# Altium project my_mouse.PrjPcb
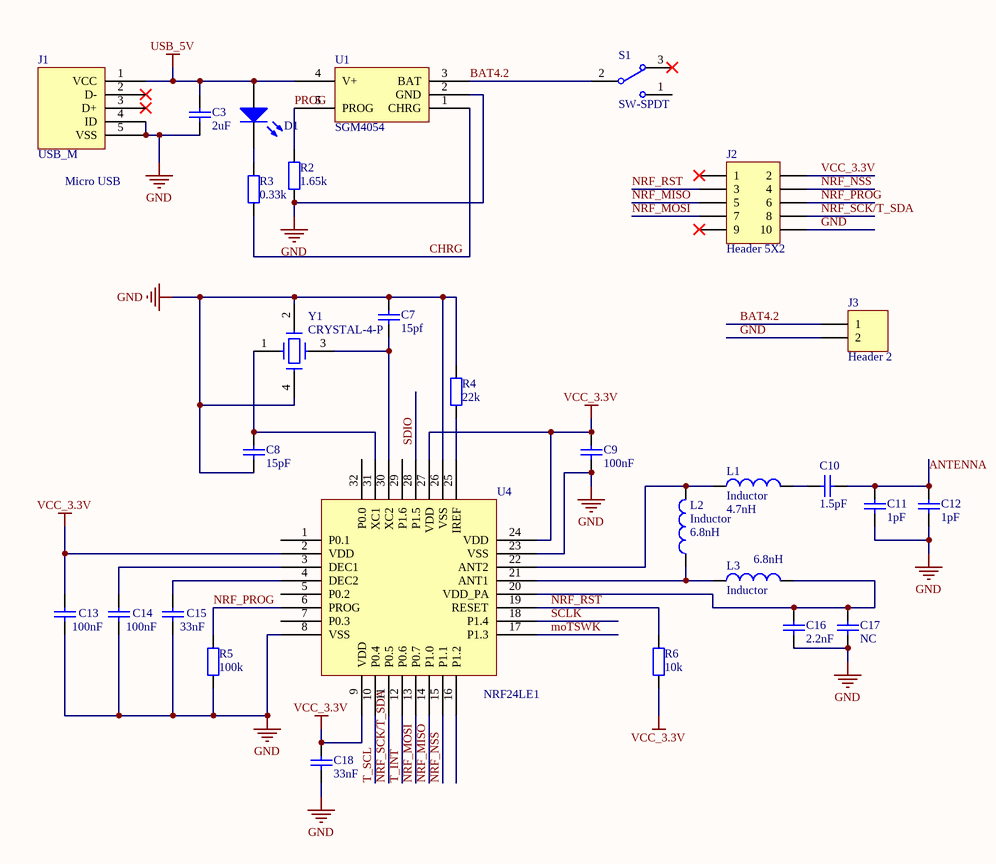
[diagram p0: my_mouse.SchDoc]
1 sheet, 29 parts. Net scope: global (net labels, ports and power ports of the same name join across sheets).
Board file: my_mouse.PcbDoc

## Sheet my_mouse.SchDoc
size A4

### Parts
C3  value 2uF  [C-0603]  (hidden comment: Cap-S)
C7  value 15pf  [0402s]  (hidden comment: Cap-S)
C8  value 15pF  [0402s]  (hidden comment: Cap-S)
C9  value 100nF  [0402s]  (hidden comment: Cap-S)
C10  value 1.5pF  [0402s]  (hidden comment: Cap-S)
C11  value 1pF  [0402s]  (hidden comment: Cap-S)
C12  value 1pF  [0402s]  (hidden comment: Cap-S)
C13  value 100nF  [0402s]  (hidden comment: X7R 16V)
C14  value 100nF  [0402s]  (hidden comment: X7R 16V)
C15  value 33nF  [0402s]  (hidden comment: X7R 16V)
C16  value 2.2nF  [0402s]  (hidden comment: Cap-S)
C17  value NC  [0402s]  (hidden comment: Cap-S)
C18  value 33nF  [0402s]  (hidden comment: Cap-S)
D1  LED0  [LED-0805]  (value not drawn)
J1  USB_M  [USB_MICRO]
J2  Header 5X2  [HEAD2X5_0.2]
J3  Header 2  [head2_2.0]
L1  Inductor  value 4.7nH  [0402s]
L2  Inductor  value 6.8nH  [0402s]
L3  Inductor  value 6.8nH  [0402s]
R2  value 1.65k  [0603-1]  (hidden comment: Res1)
R3  value 0.33k  [0603-1]  (hidden comment: Res1)
R4  value 22k  [0402s]  (hidden comment: Res1)
R5  value 100k  [0402s]  (hidden comment: Res1)
R6  value 10k  [0402s]  (hidden comment: Res1)
S1  SW-SPDT  [三脚拨动开关2]
U1  SGM4054  [SGM4054]
U4  NRF24LE1  [Nordic_QFN50P500X500X90-33N]
Y1  CRYSTAL-4-P  [OSC3225]

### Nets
GND: C3.1 C7.2 C8.1 C9.1 C11.2 C12.2 C13.1 C14.1 C15.1 C16.1 C17.1 C18.1 J1.4(ID) J1.5(VSS) J2.10 J3.2 R2.1 R4.2 R5.1 U1.2(GND) U4.8(VSS) U4.23(VSS) U4.26(VSS) Y1.2 Y1.4
USB_5V: C3.2 D1.1(A) J1.1(VCC) U1.4(V+)
VCC_3.3V: C9.2 C13.2 C18.2 J2.2 R6.1 U4.2(VDD) U4.9(VDD) U4.24(VDD) U4.27(VDD)
ANTENNA: C10.1 C11.1 C12.1
BAT4.2: J3.1 S1.2 U1.3(BAT)
CHRG: R3.1 U1.1(CHRG)
moTSWK: U4.17(P1.3)
NRF_MISO: J2.5 U4.14(P1.0)
NRF_MOSI: J2.7 U4.13(P0.7)
NRF_NSS: J2.4 U4.15(P1.1)
NRF_PROG: J2.6 R5.2 U4.6(PROG)
NRF_RST: J2.3 R6.2 U4.19(RESET)
NRF_SCK/T_SDA: J2.8 U4.11(P0.5)
PROG: R2.2 U1.5(PROG)
SCLK: U4.18(P1.4)
SDIO: U4.28(P1.5)
T_INT: U4.12(P0.6)
T_SCL: U4.10(P0.4)
NetC7_1: C7.1 U4.30(XC2) Y1.3
NetC8_2: C8.2 U4.31(XC1) Y1.1
NetC10_2: C10.2 L1.2
NetC14_2: C14.2 U4.3(DEC1)
NetC15_2: C15.2 U4.4(DEC2)
NetC16_2: C16.2 C17.2 L3.2 U4.20(VDD_PA)
NetD1_2: D1.2(K) R3.2
NetL1_1: L1.1 L2.2 U4.22(ANT2)
NetL2_1: L2.1 L3.1 U4.21(ANT1)
NetR4_1: R4.1 U4.25(IREF)

Not connected (* = marked no-connect by the designer): J1 2(D-)* 3(D+)*; J2 1* 9*; S1 1 3*; U4 1(P0.1) 5(P0.2) 7(P0.3) 16(P1.2) 29(P1.6) 32(P0.0)

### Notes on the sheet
- (near J1) Micro USB

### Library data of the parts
C3 C7-C12 C16-C18 = Cap-S: 贴片瓷片电容
C13-C15 = Cap: Capacitor
D1 = LED0: 发光二极管
J1 = USB_M: Micro/Mini USB
J2 = Header 5X2: Header, 5-Pin, Dual row
J3 = Header 2: Header, 2-Pin
L1-L3 = Inductor: Code_IEC: 1005
R2-R6 = Res1: 贴片电阻
S1 = SW-SPDT: 开关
